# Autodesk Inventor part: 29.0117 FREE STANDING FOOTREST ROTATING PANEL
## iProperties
Created: 2007-06
Part Number: 29.0117 FREE STANDING FOOTREST ROTATING PANEL
Material: Aluminum-6061
Document SubType Name: Modeling
Designer: Andy Moles
Density: 2.71 g/cm^3
Author: Andy Moles
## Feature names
1. Base1
